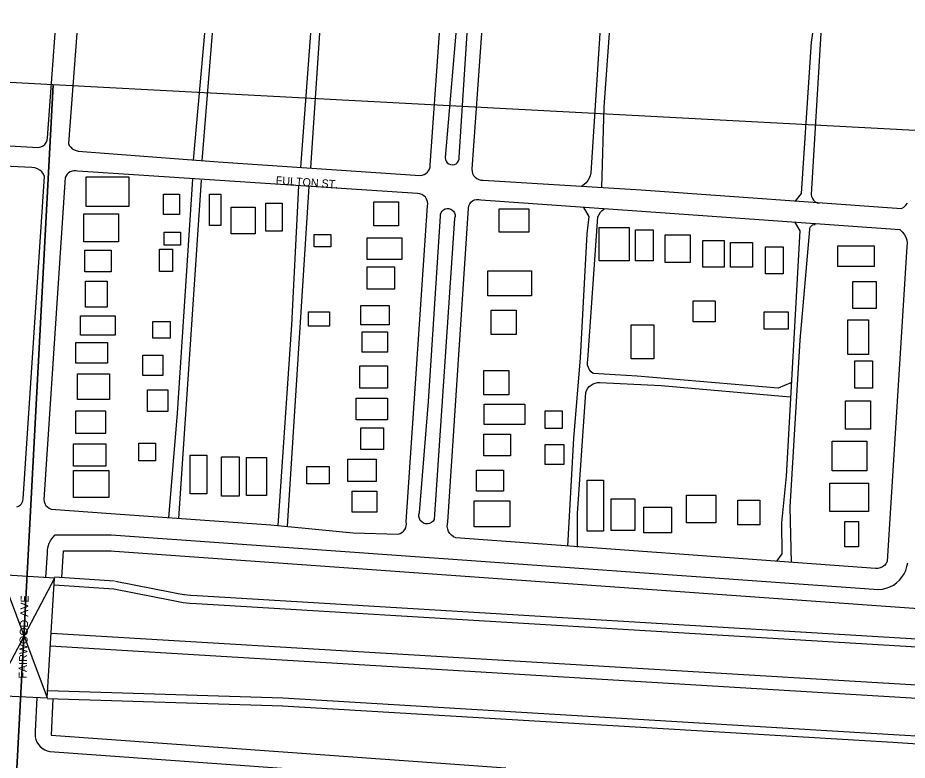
# Model space of a CAD drawing. Extents: x -9648 to 41057, y -12373 to 40276.
# Drawn here: x 17468 to 18579, y -5364 to -4437 of the extents above; entities that cross this region are included whole.
import ezdxf

# ---------------------------------------------------------------- set-up
doc = ezdxf.new("R2010")
doc.units = 0
for name, color, linetype in [('RD_P_Noise_Wall', 7, 'Continuous'), ('SC_Scratch1', 7, 'Continuous'), ('SH_Data', 7, 'Continuous')]:
    doc.layers.add(name, color=color, linetype=linetype)

msp = doc.modelspace()

# ---------------------------------------------------------------- linework, layer by layer
at = {"layer": 'RD_P_Noise_Wall'}
for p, q in [((17523.3, -5136.1), (17525.3, -5102.6)), ((17525.3, -5102.6), (17584.9, -5102.5)), ((17583.5, -5102.4), (19164.2, -5215.3)), ((17511.8, -5287.4), (17509.7, -5332.9)), ((17509.7, -5332.9), (18077.6, -5373.7))]:
    msp.add_line(p, q, dxfattribs=at)
at = {"layer": 'SC_Scratch1'}
for p, q in [((17512.2, -4520.7), (15927.4, -4436.9)), ((17431, -6058.5), (17512.2, -4520.7)), ((17512.2, -4520.7), (17431, -6058.5)), ((19097, -4604.4), (17512.2, -4520.7)), ((17514.1, -5136.5), (17436.9, -5282.9)), ((17447.3, -5132.5), (17504.7, -5286.1))]:
    msp.add_line(p, q, dxfattribs=at)
at = {"layer": 'SH_Data'}
for p, q in [((17505.1, -4586.9), (17514.7, -4456.3)), ((17542.1, -4456.3), (17531.3, -4594.1)), ((17687.5, -4614.8), (17701.9, -4456.3)), ((17698.3, -4615.5), (17711.4, -4456.3)), ((17833.5, -4456.3), (17821.3, -4623.7)), ((17833.9, -4624.5), (17845.3, -4456.3)), ((17983.3, -4620.9), (17994.9, -4456.3)), ((18015.2, -4456.3), (18001.9, -4611.5)), ((18019.3, -4610.9), (18029.5, -4456.3)), ((18047.1, -4456.3), (18035.3, -4625.9)), ((18195.1, -4456.3), (18183.7, -4630.7)), ((18200.5, -4548.3), (18207.1, -4456.3)), ((18471.1, -4456.3), (18458.9, -4657.5)), ((18459.1, -4467.5), (18461.1, -4456.3)), ((18446.9, -4656.3), (18459.1, -4467.5)), ((18197.5, -4648.7), (18200.5, -4548.3)), ((17108.4, -4579.2), (17494.1, -4598.7)), ((17504.8, -4589.9), (17505.1, -4586.9)), ((17497, -4598.2), (17499.8, -4597)), ((17499.8, -4597), (17502.1, -4595.1)), ((17502.1, -4595.1), (17503.8, -4592.7)), ((17503.8, -4592.7), (17504.8, -4589.9)), ((17531.3, -4594.1), (17532.5, -4596.5)), ((17532.5, -4596.5), (17534.2, -4598.6)), ((17494.1, -4598.7), (17497, -4598.2)), ((17534.2, -4598.6), (17536.2, -4600.4)), ((17536.2, -4600.4), (17538.5, -4601.8)), ((17538.5, -4601.8), (17541, -4602.8)), ((17541, -4602.8), (17543.7, -4603.3)), ((17543.7, -4603.3), (17718.5, -4616.9)), ((17485.9, -4624), (17230.3, -4611.7)), ((17718.5, -4616.9), (17970.7, -4633.7)), ((18001.9, -4611.5), (18002.1, -4613.9)), ((18002.1, -4613.9), (18003, -4616.1)), ((18003, -4616.1), (18004.5, -4618)), ((18004.5, -4618), (18006.4, -4619.4)), ((18006.4, -4619.4), (18008.6, -4620.2)), ((18008.6, -4620.2), (18010.9, -4620.5)), ((18010.9, -4620.5), (18013.3, -4620.1)), ((18013.3, -4620.1), (18015.4, -4619.1)), ((18015.4, -4619.1), (18017.2, -4617.5)), ((18017.2, -4617.5), (18018.5, -4615.5)), ((18018.5, -4615.5), (18019.2, -4613.3)), ((18019.2, -4613.3), (18019.3, -4610.9)), ((17489.3, -4624.4), (17485.9, -4624)), ((17492.6, -4625.4), (17489.3, -4624.4)), ((17495.6, -4627.1), (17492.6, -4625.4)), ((17498.2, -4629.4), (17495.6, -4627.1)), ((17500.2, -4632.2), (17498.2, -4629.4)), ((17531.7, -4630.7), (17529.9, -4632.4)), ((17533.7, -4629.4), (17531.7, -4630.7)), ((17536, -4628.5), (17533.7, -4629.4)), ((17538.3, -4628.1), (17536, -4628.5)), ((17540.7, -4628.1), (17538.3, -4628.1)), ((17543.1, -4628.5), (17540.7, -4628.1)), ((17967.1, -4656.5), (17543.1, -4628.5)), ((17977.8, -4631.5), (17979.7, -4629.9)), ((17979.7, -4629.9), (17981.2, -4628)), ((17981.2, -4628), (17982.4, -4625.8)), ((17982.4, -4625.8), (17983.1, -4623.4)), ((17983.1, -4623.4), (17983.3, -4620.9)), ((18035.3, -4625.9), (18035.4, -4628.7)), ((18035.4, -4628.7), (18036.1, -4631.3)), ((18036.1, -4631.3), (18037.4, -4633.8)), ((18183.7, -4630.7), (18183, -4634.1)), ((17474.7, -5037.7), (17501.7, -4635.3)), ((17501.7, -4635.3), (17500.2, -4632.2)), ((17527.5, -4636.5), (17500.7, -5038.5)), ((17528.5, -4634.3), (17527.5, -4636.5)), ((17529.9, -4632.4), (17528.5, -4634.3)), ((17667.7, -4930.5), (17686.7, -4638.4)), ((17669.3, -5062), (17697.5, -4639.5)), ((17970.7, -4633.7), (17973.2, -4633.4)), ((17973.2, -4633.4), (17975.6, -4632.7)), ((17975.6, -4632.7), (17977.8, -4631.5)), ((18037.4, -4633.8), (18039.2, -4635.9)), ((18039.2, -4635.9), (18041.3, -4637.6)), ((18041.3, -4637.6), (18043.8, -4638.8)), ((18043.8, -4638.8), (18046.5, -4639.5)), ((18046.5, -4639.5), (18049.3, -4639.5)), ((18049.3, -4639.5), (18246.5, -4651.7)), ((18180, -4640.3), (18177.8, -4642.9)), ((18181.7, -4637.3), (18180, -4640.3)), ((18183, -4634.1), (18181.7, -4637.3)), ((17804.9, -5071.9), (17832.1, -4647.5)), ((17818.9, -4646.6), (17809.9, -4820.3)), ((18175.3, -4645.2), (18172.4, -4647.1)), ((18177.8, -4642.9), (18175.3, -4645.2)), ((18246.5, -4651.7), (18571.7, -4675.1)), ((17969.9, -4656.8), (17967.1, -4656.5)), ((17972.7, -4657.7), (17969.9, -4656.8)), ((17975.1, -4659.1), (17972.7, -4657.7)), ((17977.1, -4661.1), (17975.1, -4659.1)), ((17978.7, -4663.5), (17977.1, -4661.1)), ((17979.7, -4666.2), (17978.7, -4663.5)), ((18036.1, -4665.5), (18038.5, -4664.3)), ((18038.5, -4664.3), (18041, -4663.7)), ((18041, -4663.7), (18043.7, -4663.7)), ((18043.7, -4663.7), (18046.3, -4664.3)), ((18046.3, -4664.3), (18276.5, -4680.5)), ((18438.8, -4666.3), (18446.9, -4656.3)), ((18458.9, -4657.5), (18459.3, -4660.1)), ((18459.3, -4660.1), (18460.4, -4662.6)), ((18460.4, -4662.6), (18461.9, -4664.8)), ((18461.9, -4664.8), (18463.9, -4666.6)), ((17953.3, -5066.3), (17979.7, -4671.9)), ((17980, -4669.1), (17979.7, -4666.2)), ((17979.7, -4671.9), (17980, -4669.1)), ((17999.8, -4676.6), (18001.9, -4675.6)), ((18001.9, -4675.6), (18004.2, -4675)), ((18004.2, -4675), (18006.5, -4675.1)), ((18005.3, -5066.3), (18031.1, -4674.5)), ((18006.5, -4675.1), (18008.8, -4675.8)), ((18008.8, -4675.8), (18010.8, -4677)), ((18031.1, -4674.5), (18031.5, -4671.9)), ((18031.5, -4671.9), (18032.5, -4669.4)), ((18032.5, -4669.4), (18034.1, -4667.2)), ((18034.1, -4667.2), (18036.1, -4665.5)), ((18174.5, -4673.7), (18181.3, -4685.1)), ((18198, -4677.4), (18200.6, -4675.4)), ((18463.9, -4666.6), (18466.3, -4667.8)), ((18466.3, -4667.8), (18468.9, -4668.5)), ((18571.7, -4675.1), (18574.6, -4673.3)), ((18574.6, -4673.3), (18577.1, -4671.1)), ((18577.1, -4671.1), (18579.1, -4668.4)), ((17980.9, -4916.1), (17995.9, -4684.7)), ((17995.9, -4684.7), (17996.1, -4682.4)), ((17996.1, -4682.4), (17996.8, -4680.2)), ((17996.8, -4680.2), (17998.1, -4678.2)), ((17998.1, -4678.2), (17999.8, -4676.6)), ((18010.8, -4677), (18012.4, -4678.6)), ((18012.4, -4678.6), (18013.6, -4680.6)), ((18013.6, -4680.6), (18014.2, -4682.9)), ((18014.3, -4685.2), (18013.7, -4687.5)), ((18014.2, -4682.9), (18014.3, -4685.2)), ((18181.3, -4685.1), (18178.7, -4706.9)), ((18179.9, -4864.1), (18192.5, -4685.3)), ((18192.5, -4685.3), (18194, -4682.4)), ((18194, -4682.4), (18195.8, -4679.8)), ((18195.8, -4679.8), (18198, -4677.4)), ((18276.5, -4680.5), (18569.5, -4701.5)), ((18013.7, -4687.5), (17988.1, -5063.3)), ((18437.9, -4691.8), (18444.7, -4703.1)), ((18457.4, -4699.7), (18458.1, -4698.1)), ((18458.1, -4698.1), (18459.1, -4696.7)), ((18459.1, -4696.7), (18460.5, -4695.6)), ((18460.5, -4695.6), (18462.2, -4695)), ((18462.2, -4695), (18463.9, -4694.9)), ((18178.7, -4706.9), (18170.3, -4861.5)), ((18444.7, -4703.1), (18427.7, -5009.1)), ((18445.1, -4839.3), (18457.3, -4701.5)), ((18457.3, -4701.5), (18457.4, -4699.7)), ((18569.5, -4701.5), (18572.6, -4704.1)), ((18572.6, -4704.1), (18575.1, -4707.2)), ((18575.1, -4707.2), (18577, -4710.7)), ((18577, -4710.7), (18578.2, -4714.5)), ((18578.2, -4714.5), (18578.6, -4718.5)), ((18578.6, -4718.5), (18578.3, -4722.5)), ((18578.3, -4722.5), (18553.7, -5115.9)), ((17809.9, -4820.3), (17793.1, -5070.8)), ((18432.5, -5048.1), (18445.1, -4839.3)), ((18170.3, -4861.5), (18162.1, -4962.3)), ((18179.5, -4867.3), (18179.9, -4864.1)), ((18179.7, -4870.5), (18179.5, -4867.3)), ((18180.7, -4873.6), (18179.7, -4870.5)), ((18182.2, -4876.4), (18180.7, -4873.6)), ((18184.2, -4878.9), (18182.2, -4876.4)), ((18186.7, -4880.9), (18184.2, -4878.9)), ((18241.7, -4884.3), (18186.7, -4880.9)), ((18417.7, -4899.5), (18241.7, -4884.3)), ((18179.9, -4899.6), (18181.8, -4897.4)), ((18181.8, -4897.4), (18184, -4895.5)), ((18184, -4895.5), (18186.5, -4894)), ((18186.5, -4894), (18189.2, -4893)), ((18189.2, -4893), (18192, -4892.4)), ((18192, -4892.4), (18194.9, -4892.3)), ((18194.9, -4892.3), (18271.7, -4895.9)), ((18271.7, -4895.9), (18432.5, -4910.1)), ((18433.4, -4892.6), (18417.7, -4899.5)), ((18167.3, -5056.1), (18177.5, -4904.9)), ((18177.5, -4904.9), (18178.5, -4902.2)), ((18178.5, -4902.2), (18179.9, -4899.6)), ((17969.9, -5054.7), (17980.9, -4916.1)), ((17656.9, -5061.2), (17667.7, -4930.5)), ((18162.1, -4962.3), (18154.5, -5096.9)), ((18427.7, -5009.1), (18421.9, -5067.5)), ((17472.6, -5043.9), (17473.8, -5042)), ((17473.8, -5042), (17474.5, -5039.9)), ((17474.5, -5039.9), (17474.7, -5037.7)), ((17500.7, -5038.5), (17501, -5041.1)), ((17501, -5041.1), (17501.9, -5043.6)), ((17467.1, -5047.5), (17469.2, -5046.7)), ((17469.2, -5046.7), (17471.1, -5045.5)), ((17471.1, -5045.5), (17472.6, -5043.9)), ((17501.9, -5043.6), (17503.3, -5045.9)), ((17503.3, -5045.9), (17505.1, -5047.8)), ((17505.1, -5047.8), (17507.3, -5049.3)), ((17507.3, -5049.3), (17509.7, -5050.3)), ((17509.7, -5050.3), (17584.5, -5056.1)), ((18434.5, -5117), (18432.5, -5048.1)), ((17584.5, -5056.1), (17784.1, -5069.9)), ((17969.1, -5057.2), (17969.9, -5054.7)), ((17969.1, -5059.8), (17969.1, -5057.2)), ((17969.6, -5062.3), (17969.1, -5059.8)), ((17970.8, -5064.6), (17969.6, -5062.3)), ((17972.6, -5066.5), (17970.8, -5064.6)), ((17988.1, -5063.3), (17986.7, -5065.5)), ((18166.9, -5097.9), (18167.3, -5056.1)), ((17784.1, -5069.9), (17887.1, -5080)), ((17951.4, -5076.1), (17952.6, -5073.9)), ((17952.6, -5073.9), (17953.3, -5071.4)), ((17953.6, -5068.8), (17953.3, -5066.3)), ((17953.3, -5071.4), (17953.6, -5068.8)), ((17974.8, -5067.9), (17972.6, -5066.5)), ((17977.2, -5068.7), (17974.8, -5067.9)), ((17979.8, -5068.9), (17977.2, -5068.7)), ((17982.4, -5068.3), (17979.8, -5068.9)), ((17984.7, -5067.2), (17982.4, -5068.3)), ((17986.7, -5065.5), (17984.7, -5067.2)), ((18004.5, -5072.3), (18004.6, -5069.3)), ((18005, -5075.4), (18004.5, -5072.3)), ((18004.6, -5069.3), (18005.3, -5066.3)), ((18006.1, -5078.2), (18005, -5075.4)), ((18421.9, -5067.5), (18422.3, -5106.3)), ((17509.4, -5089.3), (17511.8, -5085.8)), ((17511.8, -5085.8), (17514.7, -5082.7)), ((17514.7, -5082.7), (17584.9, -5082.5)), ((17584.9, -5082.5), (18542.9, -5150.9)), ((17887.1, -5080), (17943.1, -5081.7)), ((17943.1, -5081.7), (17945.6, -5081)), ((17945.6, -5081), (17947.8, -5079.7)), ((17947.8, -5079.7), (17949.8, -5078.1)), ((17949.8, -5078.1), (17951.4, -5076.1)), ((18007.7, -5080.8), (18006.1, -5078.2)), ((18009.8, -5083.1), (18007.7, -5080.8)), ((18012.3, -5084.9), (18009.8, -5083.1)), ((18015.1, -5086.1), (18012.3, -5084.9)), ((18539.3, -5124.5), (18015.1, -5086.1)), ((17505.3, -5101.3), (17506.1, -5097.1)), ((17506.1, -5097.1), (17507.5, -5093.1)), ((17507.5, -5093.1), (17509.4, -5089.3)), ((17503.3, -5135.9), (17505.1, -5105.5)), ((17505.1, -5105.5), (17505.3, -5101.3)), ((18422.3, -5106.3), (18415.4, -5115.6)), ((18552.3, -5118.6), (18550.4, -5120.8)), ((18553.7, -5115.9), (18552.3, -5118.6)), ((18578.5, -5122.2), (18579.4, -5117.4)), ((18542.3, -5124.5), (18539.3, -5124.5)), ((18545.2, -5123.9), (18542.3, -5124.5)), ((18548, -5122.7), (18545.2, -5123.9)), ((18550.4, -5120.8), (18548, -5122.7)), ((18574.9, -5131.3), (18577, -5126.9)), ((18577, -5126.9), (18578.5, -5122.2)), ((17514.1, -5136.5), (17447.3, -5132.5)), ((17504.7, -5286.1), (17514.1, -5136.5)), ((17588.9, -5140.5), (17514.1, -5135.5)), ((17660, -5154.5), (17590.2, -5140.7)), ((18565.5, -5142.5), (18569.1, -5139.1)), ((18569.1, -5139.1), (18572.2, -5135.4)), ((18572.2, -5135.4), (18574.9, -5131.3)), ((17588.3, -5150.5), (17513.5, -5145.5)), ((17658.1, -5164.3), (17588.3, -5150.5)), ((18542.9, -5150.9), (18547.8, -5150.4)), ((18547.8, -5150.4), (18552.5, -5149.3)), ((18552.5, -5149.3), (18557.1, -5147.6)), ((18557.1, -5147.6), (18561.5, -5145.3)), ((18561.5, -5145.3), (18565.5, -5142.5)), ((17666.4, -5166), (17658.1, -5164.3)), ((17668.4, -5156.2), (17660.1, -5154.5)), ((17676.2, -5157.4), (17667.9, -5156.1)), ((17684.1, -5158.2), (17675.7, -5157.3)), ((17692.1, -5158.7), (17683.7, -5158.2)), ((18959, -5234.9), (17692.1, -5158.7)), ((17674.7, -5167.3), (17666.4, -5166)), ((17683.1, -5168.2), (17674.7, -5167.3)), ((17691.5, -5168.7), (17683.1, -5168.2)), ((18958.4, -5244.9), (17691.5, -5168.7)), ((17509.8, -5205.5), (18697.7, -5276.1)), ((18733.1, -5295.5), (17508.7, -5221.7)), ((17436.9, -5282.9), (17504.7, -5286.1)), ((17491.9, -5285.5), (17489.9, -5328.1)), ((17799.3, -5286.5), (17505.3, -5277.2)), ((18561.5, -5332.1), (17799.3, -5286.5)), ((17799, -5296.5), (17505, -5287.2)), ((18560.9, -5342), (17798.7, -5296.4)), ((17489.9, -5328.1), (17489.7, -5331.5)), ((17489.7, -5331.5), (17489.9, -5334.9)), ((17489.9, -5334.9), (17490.8, -5338.3)), ((17490.8, -5338.3), (17492.1, -5341.4)), ((17492.1, -5341.4), (17493.9, -5344.3)), ((18757.8, -5355.2), (18560.8, -5342)), ((18758.5, -5345.3), (18561.5, -5332.1)), ((17493.9, -5344.3), (17496.2, -5346.9)), ((17496.2, -5346.9), (17498.8, -5349.1)), ((17498.8, -5349.1), (17501.8, -5350.9)), ((17501.8, -5350.9), (17505, -5352.1)), ((17505, -5352.1), (17508.3, -5352.9)), ((17508.3, -5352.9), (18076.2, -5393.7))]:
    msp.add_line(p, q, dxfattribs=at)
for points in [[(17553.4, -4635.7), (17606.7, -4635.7), (17606.7, -4672.6), (17553.4, -4672.6)], [(17650.1, -4657), (17670, -4657), (17670, -4682.6), (17650.1, -4682.6)], [(17707.6, -4657), (17721.8, -4657), (17721.8, -4696.1), (17707.6, -4696.1)], [(17734.6, -4673.3), (17764.4, -4673.3), (17764.4, -4706.7), (17734.6, -4706.7)], [(17777.9, -4668.4), (17798.5, -4668.4), (17798.5, -4703.2), (17777.9, -4703.2)], [(17912.9, -4666.9), (17943.5, -4666.9), (17943.5, -4696.8), (17912.9, -4696.8)], [(18069.2, -4675.5), (18106.2, -4675.5), (18106.2, -4704.6), (18069.2, -4704.6)], [(17550.6, -4681.9), (17593.9, -4681.9), (17593.9, -4716.7), (17550.6, -4716.7)], [(17650.8, -4704.6), (17671.4, -4704.6), (17671.4, -4720.9), (17650.8, -4720.9)], [(17838.3, -4707.4), (17858.9, -4707.4), (17858.9, -4723.1), (17838.3, -4723.1)], [(18194, -4698.7), (18231.7, -4698.7), (18231.7, -4740.3), (18194, -4740.3)], [(18239.6, -4701.9), (18261.5, -4701.9), (18261.5, -4740.3), (18239.6, -4740.3)], [(18276.4, -4708.1), (18307.8, -4708.1), (18307.8, -4742.7), (18276.4, -4742.7)], [(17904.4, -4711.7), (17947.7, -4711.7), (17947.7, -4738.7), (17904.4, -4738.7)], [(18323.5, -4715.2), (18350.2, -4715.2), (18350.2, -4748.2), (18323.5, -4748.2)], [(18358, -4717.6), (18385.5, -4717.6), (18385.5, -4748.2), (18358, -4748.2)], [(17552, -4727.3), (17584.7, -4727.3), (17584.7, -4754.3), (17552, -4754.3)], [(17645.1, -4725.9), (17661.4, -4725.9), (17661.4, -4753.6), (17645.1, -4753.6)], [(18402, -4723.1), (18423.9, -4723.1), (18423.9, -4756.8), (18402, -4756.8)], [(18492.2, -4721.5), (18537.7, -4721.5), (18537.7, -4747.4), (18492.2, -4747.4)], [(17904.4, -4747.9), (17938.5, -4747.9), (17938.5, -4775.7), (17904.4, -4775.7)], [(18055, -4752.9), (18109.7, -4752.9), (18109.7, -4784.2), (18055, -4784.2)], [(17552.7, -4765.7), (17579.7, -4765.7), (17579.7, -4798.4), (17552.7, -4798.4)], [(18511, -4766.2), (18540, -4766.2), (18540, -4800), (18511, -4800)], [(17896.6, -4796.3), (17932.1, -4796.3), (17932.1, -4820.4), (17896.6, -4820.4)], [(18311.7, -4790.5), (18339.2, -4790.5), (18339.2, -4816.4), (18311.7, -4816.4)], [(17546.3, -4809.1), (17589.7, -4809.1), (17589.7, -4833.2), (17546.3, -4833.2)], [(17831.2, -4804.1), (17857.5, -4804.1), (17857.5, -4821.9), (17831.2, -4821.9)], [(18059.3, -4802), (18090.5, -4802), (18090.5, -4832.5), (18059.3, -4832.5)], [(18400.4, -4803.9), (18430.2, -4803.9), (18430.2, -4825.9), (18400.4, -4825.9)], [(17636.6, -4816.2), (17658.6, -4816.2), (17658.6, -4836.8), (17636.6, -4836.8)], [(18504.7, -4814.1), (18530.6, -4814.1), (18530.6, -4857.3), (18504.7, -4857.3)], [(17898, -4829), (17930, -4829), (17930, -4854.5), (17898, -4854.5)], [(18234.1, -4820.4), (18262.3, -4820.4), (18262.3, -4862.8), (18234.1, -4862.8)], [(17540.7, -4842.5), (17580.4, -4842.5), (17580.4, -4868.1), (17540.7, -4868.1)], [(17624.5, -4858.1), (17649.4, -4858.1), (17649.4, -4883.7), (17624.5, -4883.7)], [(17895.2, -4871.6), (17930, -4871.6), (17930, -4899.3), (17895.2, -4899.3)], [(18513.4, -4865.1), (18535.3, -4865.1), (18535.3, -4899.6), (18513.4, -4899.6)], [(17542.8, -4881.6), (17582.6, -4881.6), (17582.6, -4913.5), (17542.8, -4913.5)], [(18050, -4877.3), (18081.3, -4877.3), (18081.3, -4907.8), (18050, -4907.8)], [(17630.2, -4901.5), (17655.7, -4901.5), (17655.7, -4928.5), (17630.2, -4928.5)], [(17890.9, -4912.1), (17930, -4912.1), (17930, -4939.1), (17890.9, -4939.1)], [(18050.7, -4919.2), (18101.2, -4919.2), (18101.2, -4944.8), (18050.7, -4944.8)], [(18501.6, -4915.3), (18533, -4915.3), (18533, -4950.7), (18501.6, -4950.7)], [(17540.7, -4927.7), (17577.6, -4927.7), (17577.6, -4956.2), (17540.7, -4956.2)], [(18126.8, -4927.7), (18148.1, -4927.7), (18148.1, -4949.8), (18126.8, -4949.8)], [(17896.6, -4949.1), (17925, -4949.1), (17925, -4976.1), (17896.6, -4976.1)], [(18050, -4956.9), (18083.4, -4956.9), (18083.4, -4983.9), (18050, -4983.9)], [(17537.8, -4969), (17578.3, -4969), (17578.3, -4996.7), (17537.8, -4996.7)], [(17619.5, -4968.3), (17640.1, -4968.3), (17640.1, -4990.3), (17619.5, -4990.3)], [(18126.8, -4969.7), (18150.2, -4969.7), (18150.2, -4994.6), (18126.8, -4994.6)], [(18485.1, -4965.6), (18528.3, -4965.6), (18528.3, -5002.5), (18485.1, -5002.5)], [(17683.5, -4983.2), (17704.1, -4983.2), (17704.1, -5031.5), (17683.5, -5031.5)], [(17722.5, -4985.3), (17744.5, -4985.3), (17744.5, -5034.3), (17722.5, -5034.3)], [(17753.8, -4986), (17778.7, -4986), (17778.7, -5033.6), (17753.8, -5033.6)], [(17829.1, -4997.4), (17856.8, -4997.4), (17856.8, -5018.7), (17829.1, -5018.7)], [(17880.2, -4988.2), (17915.8, -4988.2), (17915.8, -5015.9), (17880.2, -5015.9)], [(17537.8, -5002.4), (17581.9, -5002.4), (17581.9, -5035.8), (17537.8, -5035.8)], [(18040.8, -5001.7), (18074.9, -5001.7), (18074.9, -5028), (18040.8, -5028)], [(18179.1, -5014.2), (18199.5, -5014.2), (18199.5, -5077.8), (18179.1, -5077.8)], [(18482, -5018.2), (18530.6, -5018.2), (18530.6, -5053.5), (18482, -5053.5)], [(17885.9, -5028), (17916.5, -5028), (17916.5, -5054.2), (17885.9, -5054.2)], [(18038, -5040), (18082.7, -5040), (18082.7, -5072.7), (18038, -5072.7)], [(18209, -5037.8), (18238.8, -5037.8), (18238.8, -5077), (18209, -5077)], [(18303.1, -5033.1), (18340, -5033.1), (18340, -5067.6), (18303.1, -5067.6)], [(18367.4, -5039.3), (18394.9, -5039.3), (18394.9, -5070), (18367.4, -5070)], [(18249.8, -5048), (18284.3, -5048), (18284.3, -5080.2), (18249.8, -5080.2)], [(18500.8, -5066), (18518.1, -5066), (18518.1, -5097.4), (18500.8, -5097.4)]]:
    msp.add_lwpolyline(points, close=True, dxfattribs=at)

# ---------------------------------------------------------------- texts
at = {"layer": 'SC_Scratch1'}
for s, rotation, p in [('FULTON ST.', 356.2218, (17790.1, -4644.7)), ('FAIRWOOD AVE', 88.5022, (17479.1, -5262.2))]:
    msp.add_text(s, height=10, rotation=rotation, dxfattribs=at).set_placement(p)

doc.saveas('drawing.dxf')
